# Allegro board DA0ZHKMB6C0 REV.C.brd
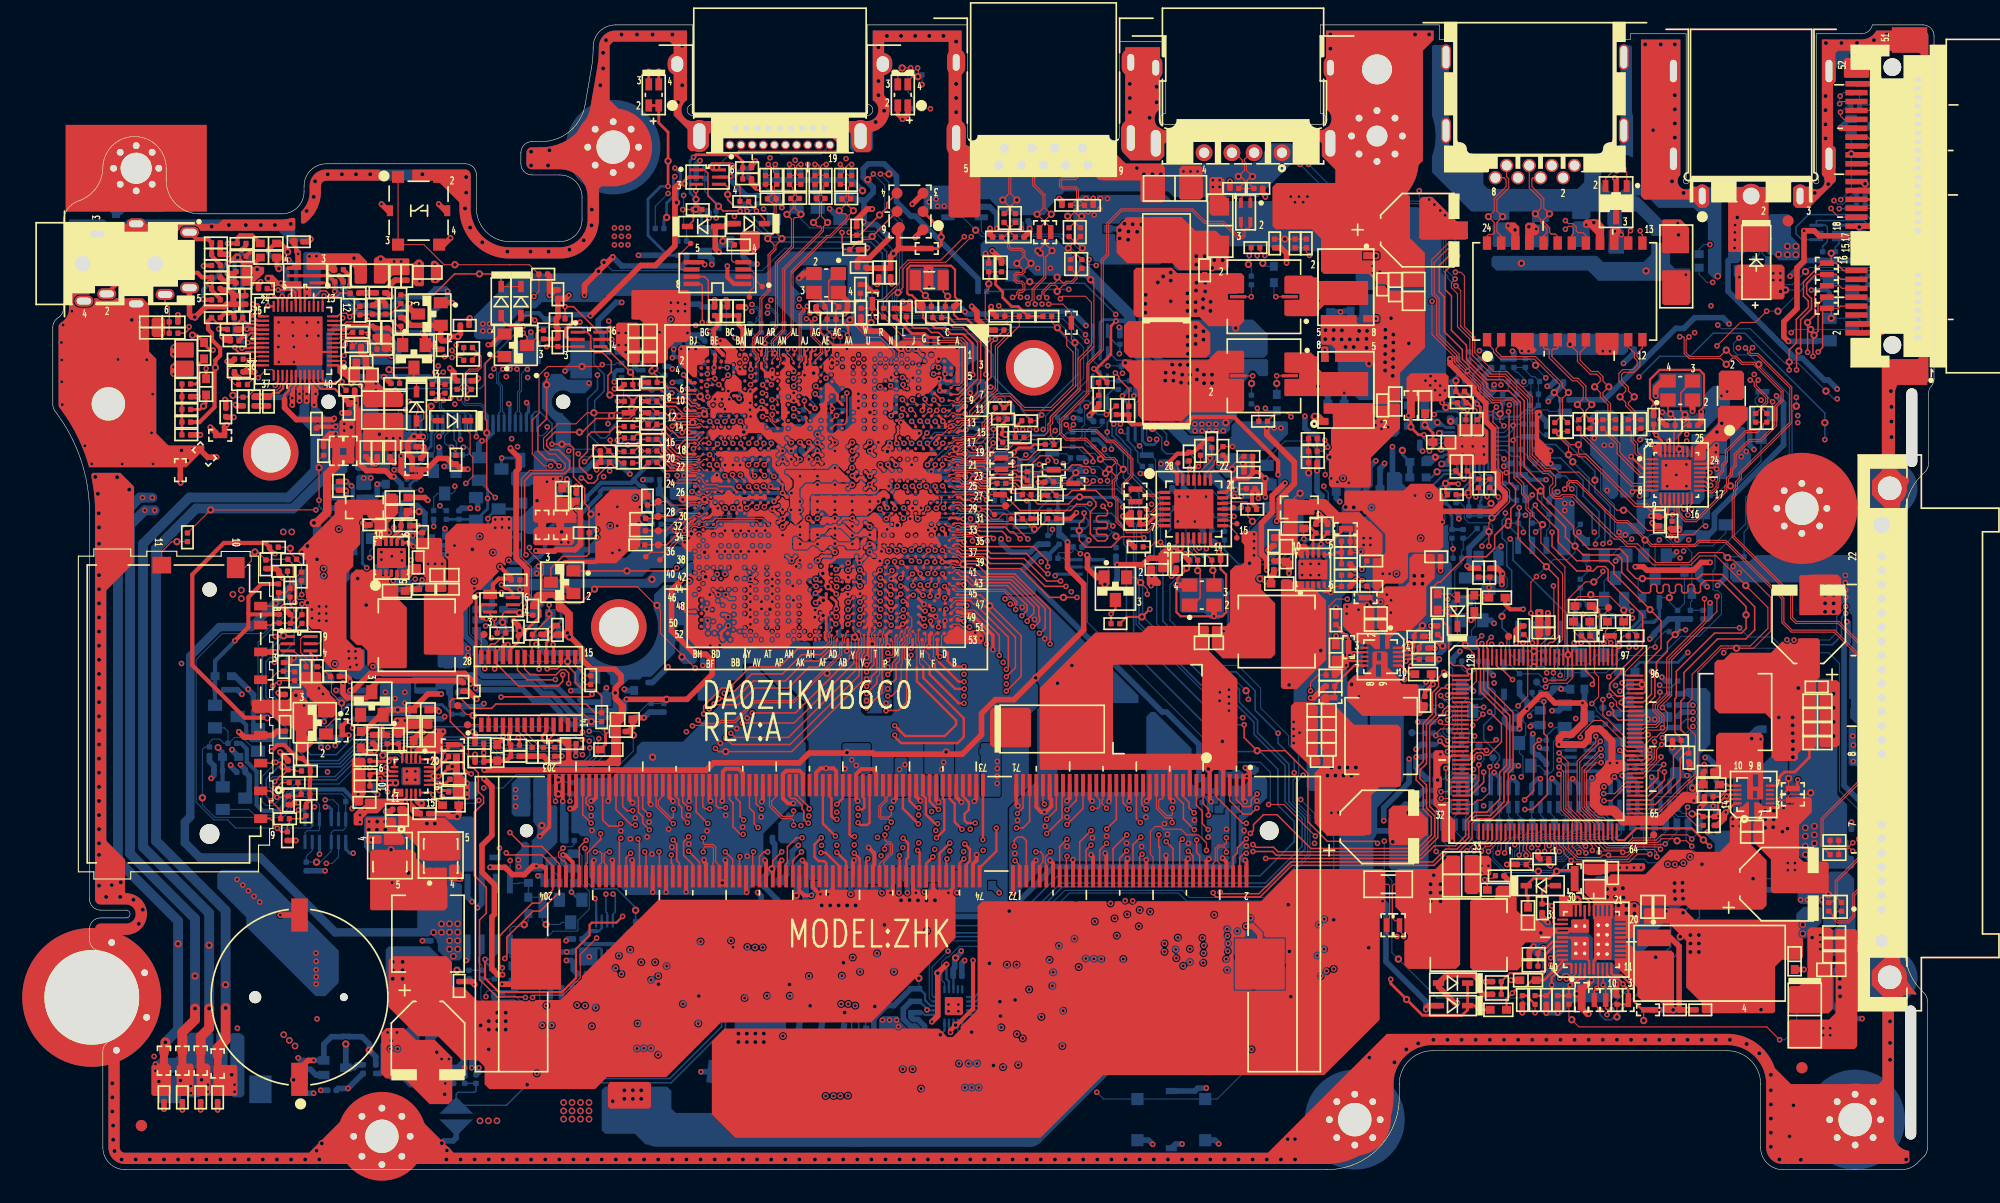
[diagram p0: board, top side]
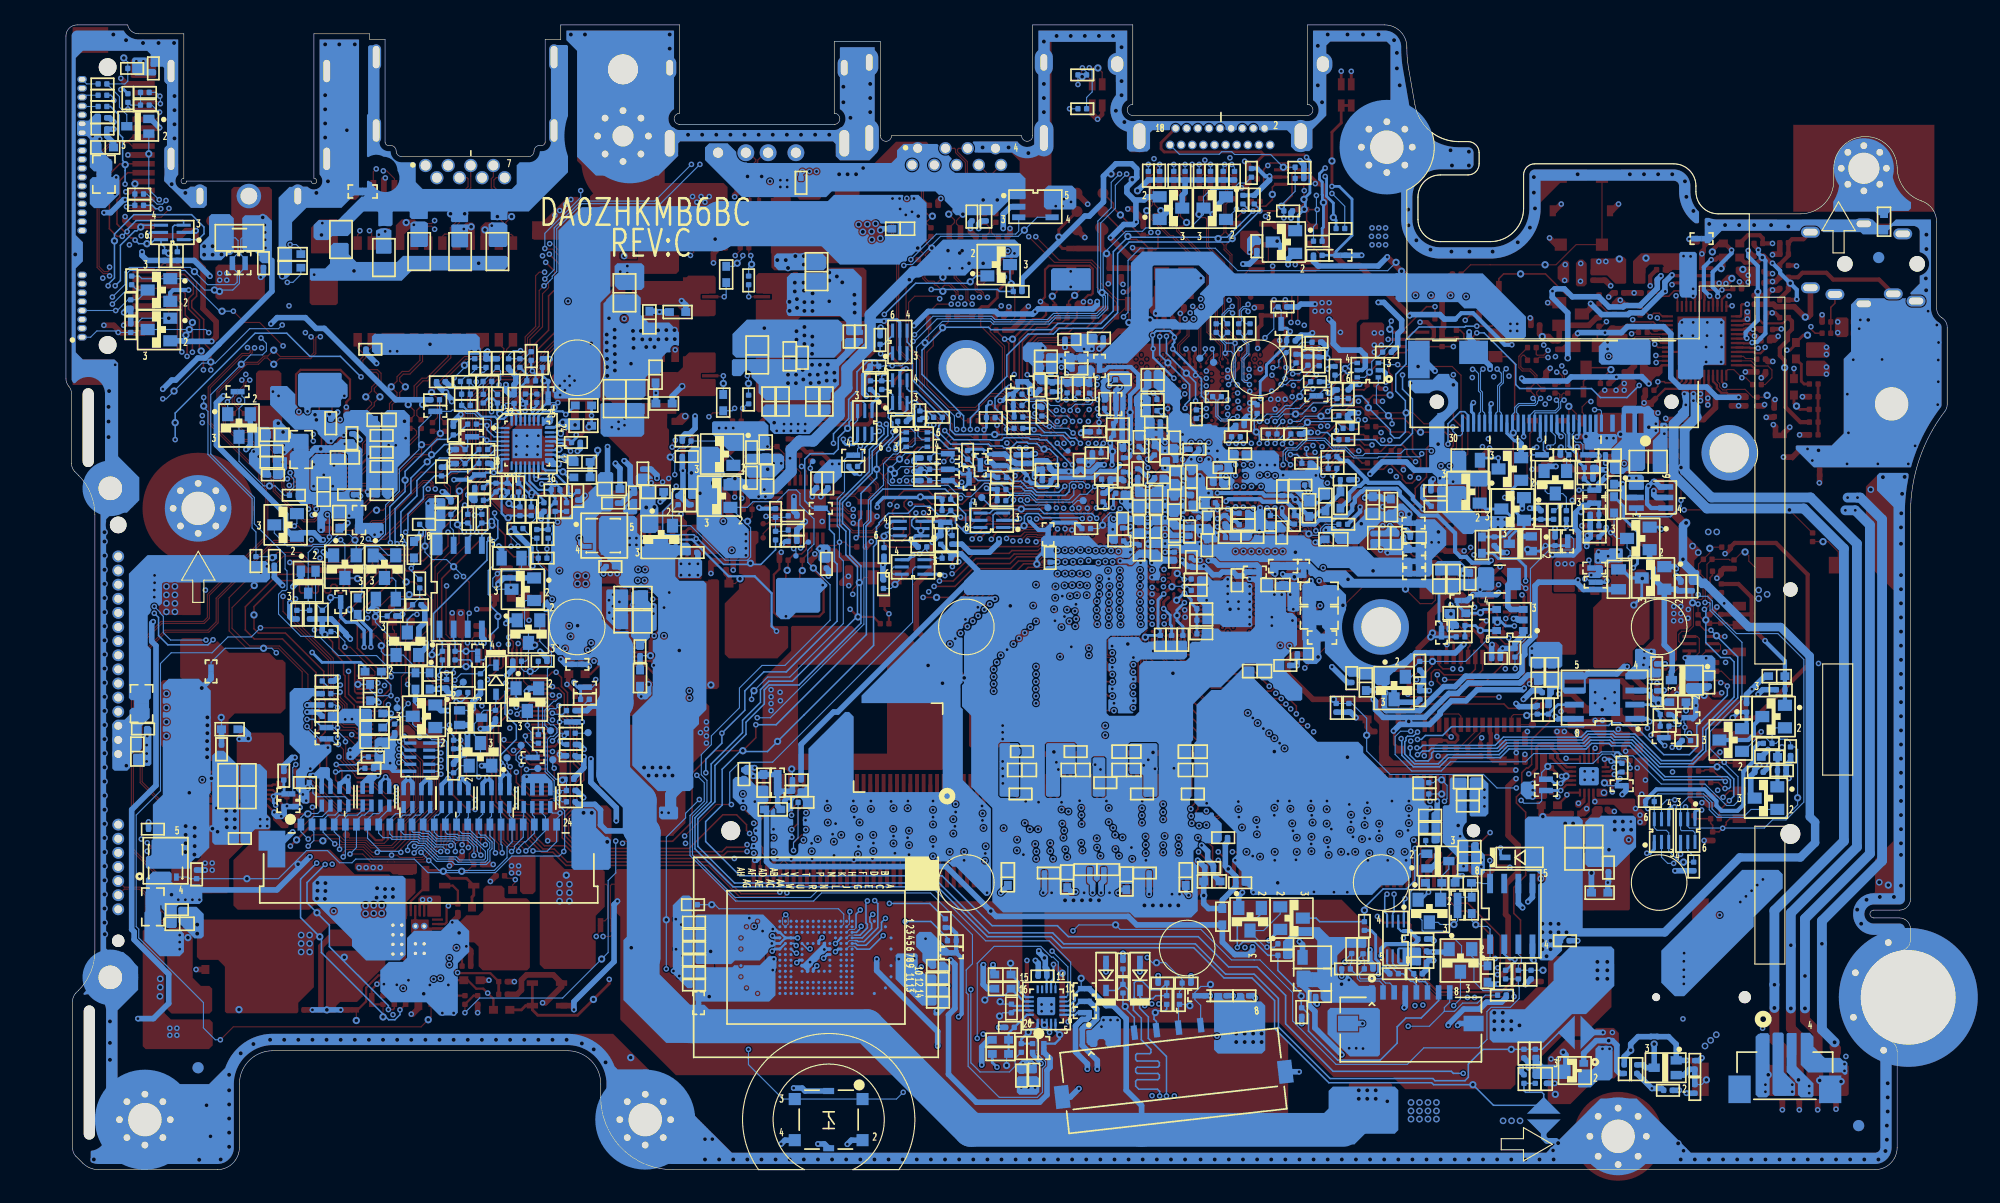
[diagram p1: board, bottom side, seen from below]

Outline 169.2 x 103 mm; copper layers: TOP, SGND, IN1, IN2, SVCC, BOTTOM. Coordinates in mm from the lower left corner of the outline.
Outline path: 0,75.8 arc(0.13,76.28) 0.47,76.65 arc(0.82,77.01) 0.95,77.5 0.95,85.27 arc(1.33,86.44) 2.32,87.17 arc(3.88,88.31) 4.5,90.15 arc(7.37,92.95) 10.2,90.1 10.2,89 arc(11.08,86.88) 13.2,86 20.6,86 arc(22.01,86.59) 22.6,88 22.6,88.5 arc(23.19,89.91) 24.6,90.5 37.1,90.5 arc(37.81,90.21) 38.1,89.5 38.1,86.5 arc(38.98,84.38) 41.1,83.5 45.6,83.5 arc(47.01,84.09) 47.6,85.5 47.6,87.5 arc(47.01,88.91) 45.6,89.5 43.1,89.5 arc(42.39,89.79) 42.1,90.5 42.1,91.5 arc(42.39,92.21) 43.1,92.5 43.93,92.5 arc(46.51,93.44) 47.87,95.82 48.45,99.15 arc(48.56,100) 48.6,100.86 48.6,101 arc(49.19,102.41) 50.6,103 57.55,103 57.55,95.85 arc(57.05,95.35) 57.55,94.85 73.25,94.85 arc(73.75,95.35) 73.25,95.85 73.25,103 82.25,103 82.25,93.03 arc(82.75,92.53) 83.25,93.03 94.95,93.03 arc(95.45,92.53) 95.95,93.03 95.95,101.5 100.1,101.5 100.1,95.05 arc(99.6,94.55) 100.1,94.05 114,94.05 arc(114.5,94.55) 114,95.05 114,103 124.7,103 124.7,101.7 126.1,101.7 126.1,92.45 arc(126.19,92.24) 126.4,92.15 126.6,92.15 arc(126.95,92) 127.1,91.65 arc(127.25,91.3) 127.6,91.15 139,91.15 arc(139.35,91.3) 139.5,91.65 arc(139.65,92) 140,92.15 140.2,92.15 arc(140.41,92.24) 140.5,92.45 140.5,101.7 141.9,101.7 141.9,102.2 146.9,102.2 146.9,89.2 arc(146.72,88.77) 147.15,88.95 158.35,88.95 arc(158.78,88.77) 158.6,89.2 158.6,102.2 162.67,102.2 arc(163.3,102.43) 163.65,103 168.2,103 arc(168.91,102.71) 169.2,102 169.2,71.16 arc(169.14,70.8) 168.95,70.5 arc(168.76,70.19) 168.7,69.83 168.7,63.51 arc(168.62,63.13) 168.41,62.81 168.06,62.46 arc(166.98,60.84) 166.6,58.93 166.6,19.67 arc(166.98,17.76) 168.06,16.14 168.31,15.89 arc(168.52,15.57) 168.6,15.19 168.6,1.91 arc(168.52,1.53) 168.31,1.21 167.69,0.59 arc(167.04,0.15) 166.27,0 155.6,0 arc(154.19,0.59) 153.6,2 153.6,7.7 arc(152.72,9.82) 150.6,10.7 124.1,10.7 arc(121.98,9.82) 121.1,7.7 121.1,6.5 arc(119.2,1.9) 114.6,0 6.5,0 arc(5.09,0.59) 4.5,2 4.5,10.65 arc(4.67,11.2) 5.12,11.57 arc(7.72,16) 4.15,19.7 arc(3.54,20.04) 3.3,20.69 3.3,21.65 arc(3.59,22.36) 4.3,22.65 6.6,22.65 arc(6.95,23) 6.6,23.35 4.3,23.35 arc(3.59,23.64) 3.3,24.35 3.3,59.11 arc(2.51,63.93) 0.21,68.24 arc(0.05,68.52) 0,68.85 0,75.8

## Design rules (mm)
constraint set DEFAULT: min track width 0.102
net group DFP-S3(3.5)W4(4)-T2B: nets C_TX1_HDMI+ C_TX1_HDMI-
net group DFP-S3W4-TB: nets SOC_PCIE_COMN SOC_PCIE_COMP
net group W5.5-T12B: nets PCH_DPST_PWM PCH_DPST_PWM_C
net group DFP-S3(3.5)W4(4)-T1: nets IN_CLK IN_CLK# IN_D0 IN_D0# IN_D1 IN_D1# IN_D2 IN_D2# SATA_RXN0 SATA_RXN0_R SATA_RXP0 SATA_RXP0_R SATA_TXN0 SATA_TXN0_R SATA_TXP0 SATA_TXP0_R
net group DFP-S3(3.5)W4(4)-T1B: nets C_TX0_HDMI+ C_TX0_HDMI- C_TX2_HDMI+ C_TX2_HDMI- C_TXC_HDMI+ C_TXC_HDMI- CLK_PCIE_LANN CLK_PCIE_LANP CLK_PCIE_WLANN CLK_PCIE_WLANP EDP_TX0#_C EDP_TX0_C GPP_TX2N_LAN GPP_TX2P_LAN ICLK_USB_TERMN_0 ICLK_USB_TERMN_1 INT_EDP_TXN0 INT_EDP_TXP0 PCIE_RXN1_WLAN PCIE_RXN2_LAN PCIE_RXP1_WLAN PCIE_RXP2_LAN PCIE_TXN1_WLAN PCIE_TXN1_WLAN_C PCIE_TXN2_LAN PCIE_TXN2_LAN_C PCIE_TXP1_WLAN PCIE_TXP1_WLAN_C PCIE_TXP2_LAN PCIE_TXP2_LAN_C USB30_RX1+ USB30_RX1+_R USB30_RX1- USB30_RX1-_R USB30_TX1+ USB30_TX1+_R USB30_TX1- USB30_TX1-_R USB_BT_N USB_BT_P USB_H1_N USB_H1_N1 USB_H1_P USB_H1_P1 USB_USB_N USB_USB_P USBP1+_CN USBP1-_CN
net group DFP-S3(3.5)W4(4)-T12B: nets M_A_CLKN0 M_A_CLKN1 M_A_CLKP0 M_A_CLKP1 M_A_DQSN0 M_A_DQSN1 M_A_DQSN2 M_A_DQSN3 M_A_DQSN4 M_A_DQSN5 M_A_DQSN6 M_A_DQSN7 M_A_DQSP0 M_A_DQSP1 M_A_DQSP2 M_A_DQSP3 M_A_DQSP4 M_A_DQSP5 M_A_DQSP6 M_A_DQSP7 SATA_RCOMP_DN SATA_RCOMP_DP SOC_DDIO_RCOMP SOC_DDIO_RCOMP_P
net group DFP-S5.5(6)W4(3.5)-T1B: nets LAN_MX0+ LAN_MX0- LAN_MX1+ LAN_MX1- LAN_MX2+ LAN_MX2- LAN_MX3+ LAN_MX3- MDI_0+ MDI_0+_C MDI_0- MDI_0-_C MDI_1+ MDI_1+_C MDI_1- MDI_1-_C MDI_2+ MDI_2+_C MDI_2- MDI_2-_C MDI_3+ MDI_3+_C MDI_3- MDI_3-_C
net group DFP-S5W10-T12B: nets VCC_AXG_SENSE VCC_SENSE VSS_AXG_SENSE VSS_SENSE
net group W5.5(5.5)-T1: nets ACZ_BCLK ACZ_RST# ACZ_RST#_AUDIO ACZ_SDIN ACZ_SDIN0 ACZ_SDOUT ACZ_SDOUT_AUDIO ACZ_SYNC ACZ_SYNC_AUDIO BIT_CLK_AUDIO
net group W5.5(5.5)-T12B: nets 5V_HSMBCK 5V_HSMBDT 8690_CLK 8690_DATA AC_PRESENT AC_PRESENT_EC AC_PRESENT_NM ACZ_RST#_AUDIO_R ACZ_SPKR BEEP_1 BRTC_EXTPAD CLK_24M_DEBUG CLK_24M_KBC CLKRUN# DMIC_CLK DMIC_DAT DNBSWON# EMMC_CLK EMMC_CMD EMMC_DATA_0 EMMC_DATA_1 EMMC_DATA_2 EMMC_DATA_3 EMMC_DATA_4 EMMC_DATA_5 EMMC_DATA_6 EMMC_DATA_7 EMMC_RCOMP EMMC_RESET H_PROCHOT# HDA_RCOMP HDMI_SCLK HDMI_SDATA I2C_0_SCL I2C_0_SDA I2C_5_SCL I2C_5_SDA I2C_6_SCL I2C_6_SCL_R I2C_6_SDA I2C_6_SDA_R ICLK_ICOMP ICLK_RCOMP LAD0 LAD1 LAD2 LAD3 LFRAME# LPC_RCOMP M_A_DM0 M_A_DM1 M_A_DM2 M_A_DM3 M_A_DM4 M_A_DM5 M_A_DM6 M_A_DM7 M_A_DQ0 M_A_DQ1 M_A_DQ2 M_A_DQ3 M_A_DQ4 M_A_DQ5 M_A_DQ6 M_A_DQ7 M_A_DQ8 M_A_DQ9 M_A_DQ10 M_A_DQ11 M_A_DQ12 M_A_DQ13 M_A_DQ14 M_A_DQ15 M_A_DQ16 M_A_DQ17 M_A_DQ18 M_A_DQ19 M_A_DQ20 M_A_DQ21 M_A_DQ22 M_A_DQ23 M_A_DQ24 M_A_DQ25 M_A_DQ26 M_A_DQ27 M_A_DQ28 M_A_DQ29 M_A_DQ30 M_A_DQ31 M_A_DQ32 M_A_DQ33 M_A_DQ34 M_A_DQ35 M_A_DQ36 M_A_DQ37 M_A_DQ38 M_A_DQ39 M_A_DQ40 M_A_DQ41 M_A_DQ42 M_A_DQ43 M_A_DQ44 M_A_DQ45 M_A_DQ46 M_A_DQ47 M_A_DQ48 M_A_DQ49 M_A_DQ50 M_A_DQ51 M_A_DQ52 M_A_DQ53 M_A_DQ54 M_A_DQ55 M_A_DQ56 M_A_DQ57 M_A_DQ58 M_A_DQ59 M_A_DQ60 M_A_DQ61 M_A_DQ62 M_A_DQ63 MBCLK MBCLK2 MBDATA MBDATA2 N16563782 N16563868 N16564009 N77651966 PCBEEP PCBEEP_EC PCH_SLP_S0# PCH_SLP_S0_N PCLK_TPM PLTRST# RSMRST# RTC_X1 RTC_X2 SDIO3_CLK SDIO3_CMD SDIO3_DATA_0 SDIO3_DATA_1 SDIO3_DATA_2 SDIO3_DATA_3 SDIO3_RCOMP SDVO_CLK SDVO_DATA SERIRQ_R SLP_S0IX# SLP_S3# SLP_S4# SMB_RUN_CLK SMB_RUN_DAT SMB_SOC_CLK SMB_SOC_DATA SMC SMD SOC_CLKOUT_0 SOC_CLKOUT_1 SOC_CLKRUN# SOC_PLTRST# SOC_PROCHOT# SOC_PWRBTN# SOC_REST_BTN SOC_SERIRQ SOC_SPI_CLK SOC_SPI_CLK_R SOC_SPI_CLK_R1 SOC_SPI_CS# SOC_SPI_CS#_R SOC_SPI_CS#_R1 SOC_SPI_MISO SOC_SPI_MISO_R SOC_SPI_MISO_R1 SOC_SPI_MOSI SOC_SPI_MOSI_R SOC_SPI_MOSI_R1 SUS_PWRDOWNACK SUSB# SUSC# SUSWARN#_EC SVID_ALERT#_SOC SVID_CLK_SOC SVID_DATA_SOC VR_SVID_ALERT# VR_SVID_CLK VR_SVID_DATA WLAN_CLK_SCLK WLAN_CLK_SDATA XIN XOUT XTAL1 XTAL2 XTAL25_IN XTAL25_OUT
net group W8.5(8)-T12B: nets M_A_A0 M_A_A1 M_A_A2 M_A_A3 M_A_A4 M_A_A5 M_A_A6 M_A_A7 M_A_A8 M_A_A9 M_A_A10 M_A_A11 M_A_A12 M_A_A13 M_A_A14 M_A_A15 M_A_BS#0 M_A_BS#1 M_A_BS#2 M_A_CAS# M_A_CKE0 M_A_CKE1 M_A_CS#0 M_A_CS#1 M_A_ODT0 M_A_ODT1 M_A_RAS# M_A_WE#
net group W10-T12B: nets +1.8V_S5 +1.35V +3V_MINI1_VDD +VSDIO CPU_VREF DRAM_RCOMP0 DRAM_RCOMP1 DRAM_RCOMP2 HDMI_5V MIC1_INT_L MIC1_INT_L_C MIC1_INT_R MIC1_INT_R_C MIC1_INTL1 PCU_V3P3_G3_PWR TPM_VDD USB_HSIC_RCOMP
net group W15-T12B: nets +1.8V +3V_USB HPL HPL-1_TIP_SENSE HPR HPR_SYS INT_AMIC-VREFO LINE1-L LINE1-R LINE1-VREFO-L LINE1-VREFO-R MIC2-VREFO USB3_V1P0_G3 USB_RCOMP
net group W20-T12B: nets +3V_RTC +3V_S5 CCD_PWR VCCRTC_1 VCCRTC_2 VCCRTC_3 VCCRTC_4
net group W30-T12B: nets +3VPCU_EC CODEC_VREF LAN_MCT0 LAN_MCT1 LAN_MCT2 LAN_MCT3
net group W35-T12B: nets L_SPK+ L_SPK+_1 L_SPK- L_SPK-_1 MIC2_MIC_RING2_MIC MIC2_MIC_SLEEVE_MIC R_SPK+ R_SPK+_1 R_SPK- R_SPK-_1 RING2 SLEEVE
net group W40-T12B: nets +5VA LANVCC REGOUT VDD10 VDDREG/VDD33
net group W60-T12B: nets V_BLIGHT
net group W80-T12B: nets 5VUSB_0 +5V_HDD +LCDVCC
net group W90-T12B: nets LANCT3

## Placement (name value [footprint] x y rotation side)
C4  em@0.1u/10v_4  [CC0402]  112.71 16.6 0 bottom
C5  em@1u/6.3v_4  [CC0402]  90.79 16.08 0 bottom
C7  *220p/50v_4  [CC0402]  62.45 89.14 180 top
C8  0.1u/10v_4  [CC0402]  64.1 89.05 270 top
C9  0.1u/10v_4  [CC0402]  65.12 89.05 270 top
C10  0.1u/10v_4  [CC0402]  66.26 89.05 270 top
C11  0.1u/10v_4  [CC0402]  67.28 89.05 270 top
C12  0.1u/10v_4  [CC0402]  68.55 89.05 270 top
C13  0.1u/10v_4  [CC0402]  69.56 89.05 270 top
C14  0.1u/10v_4  [CC0402]  70.83 89.05 270 top
C15  0.1u/10v_4  [CC0402]  71.85 89.05 270 top
C16  10u/6.3v_4  [CC0402]  75.35 80.72 270 top
C17  *1.6p/50v_4  [CC0402]  91.15 86.77 0 top
C18  *1.6p/50v_4  [CC0402]  93.18 86.77 180 top
C19  0.1u/10v_4  [CC0402]  74.29 80.72 270 top
C20  100u/6.3v_1206  [CC1206]  100.93 88.29 0 top
C21  100u/6.3v_1206  [CC1206]  104.99 84.94 270 top
C22  *1.6p/50v_4  [CC0402]  84.93 83.91 0 top
C23  *1.6p/50v_4  [CC0402]  86.97 83.91 180 top
C24  330p/50v_4  [CC0402]  14.67 79.27 0 top
C25  0.1u/10v_4  [CC0402]  91.53 81.48 270 top
C26  0.1u/10v_4  [CC0402]  92.55 81.48 270 top
C27  *1000p/50v_4  [CC0402]  22.11 83.49 180 top
C28  220p/3kv_1808  [CC1808]  146.02 81.31 90 top
C30  em@0.1u/10v_4  [CC0402]  90.77 15.06 180 bottom
C31  330p/50v_4  [CC0402]  8.83 75.26 180 top
C32  12p/50v_4  [CC0402]  69.05 77.62 0 top
C33  12p/50v_4  [CC0402]  71.09 77.62 180 top
C34  em@0.1u/10v_4  [CC0402]  112.71 19.98 0 bottom
C35  10u/6.3v_4  [CC0402]  18.89 79.27 0 top
C36  10u/6.3v_4  [CC0402]  16.86 80.8 0 top
C37  *1000p/50v_4  [CC0402]  29.48 78.89 180 top
C38  0.01u/16v_4  [CC0402]  45.43 78.77 270 top
C39  0.1u/10v_4  [CC0402]  16.86 79.78 0 top
C40  1u/10v_4  [CC0402]  27.63 77.29 90 top
C41  100p/50v_4  [CC0402]  29.91 77.37 270 top
C42  1u/6.3v_4  [CC0402]  59.53 77.24 90 top
C43  1u/6.3v_4  [CC0402]  60.67 77.24 90 top
C44  1u/6.3v_4  [CC0402]  61.69 77.24 270 top
C45  0.1u/10v_4  [CC0402]  76.78 77.11 270 top
C46  15p/50v_4  [CC0402]  80.66 77.67 0 top
C47  15p/50v_4  [CC0402]  78.63 77.67 180 top
C48  330p/50v_4  [CC0402]  14.67 83.39 0 top
C49  10u/6.3v_4  [CC0402]  16.7 76.66 0 top
C50  10u/6.3v_6  [CC0603]  53.05 75.46 0 top
C51  0.1u/10v_4  [CC0402]  29 75.34 90 top
C52  10u/6.3v_4  [CC0402]  30.09 75.34 90 top
C53  2.2u/6.3v_4  [CC0402]  16.09 75.59 180 top
C55  *22p/50v_4  [CC0402]  27.32 74.04 0 top
C56  10u/6.3v_4  [CC0402]  29.56 73.81 180 top
C57  1u/10v_4  [CC0402]  16.73 72.92 0 top
C58  10u/6.3v_6  [CC0603]  53.05 72.92 0 top
C59  0.1u/10v_4  [CC0402]  27.75 72.7 180 top
C60  em@1u/6.3v_4  [CC0402]  90.8 17.2 0 bottom
C61  10u/6.3v_4  [CC0402]  16.73 71.78 0 top
C62  10u/6.3v_6  [CC0603]  27.96 71.5 180 top
C63  1u/10v_4  [CC0402]  17.11 70.64 0 top
C64  0.1u/10v_4  [CC0402]  37.35 72.82 0 top
C65  0.1u/10v_4  [CC0402]  37.35 73.97 0 top
C66  0.1u/10v_4  [CC0402]  34.13 70.26 270 top
C67  0.1u/10v_4  [CC0402]  35.27 70.26 270 top
C68  10u/6.3v_4  [CC0402]  17.11 69.11 270 top
C69  0.1u/10v_4  [CC0402]  18.13 69.11 90 top
C70  10u/6.3v_4  [CC0402]  19.4 69.11 90 top
C71  0.1u/10v_4  [CC0402]  23.71 67.11 90 top
C72  0.1u/10v_4  [CC0402]  26.64 68.48 90 top
C73  22u/6.3v_8  [CC0805]  28.79 68.35 270 top
C74  2.2u/10v_8  [CC0805]  30.83 68.35 90 top
C75  em@0.1u/10v_4  [CC0402]  112.71 17.72 0 bottom
C76  0.1u/10v_4  [CC0402]  153.15 67.64 270 top
C77  0.1u/10v_4  [CC0402]  154.17 67.64 270 top
C78  12p/50v_4  [CC0402]  145.53 66.98 0 top
C79  12p/50v_4  [CC0402]  147.57 66.98 180 top
C80  *22p/50v_4  [CC0402]  20.74 45.24 270 top
C82  1000p/50v_4  [CC0402]  32.3 65.05 0 top
C83  *0.1u/10v_4  [CC0402]  28.16 64.54 270 top
C84  0.1u/10v_4  [CC0402]  29.18 64.54 270 top
C85  0.01u/25v_4  [CC0402]  30.32 64.54 90 top
C86  *10p/50v_4  [CC0402]  32.71 64.01 180 top
C87  0.1u/10v_4  [CC0402]  107.53 62.76 180 top
C89  1u/6.3v_4  [CC0402]  25.7 61.53 90 top
C90  1u/6.3v_4  [CC0402]  97.37 59.08 180 top
C91  0.1u/10v_4  [CC0402]  144.49 58.32 90 top
C92  1u/6.3v_4  [CC0402]  97.37 58.06 180 top
C94  0.1u/10v_4  [CC0402]  101.06 54.51 270 top
C95  18p/50v_4  [CC0402]  102.58 54.84 0 top
C96  18p/50v_4  [CC0402]  104.64 54.84 180 top
C97  0.1u/10v_4  [CC0402]  128.24 53.72 270 top
C98  0.1u/10v_4  [CC0402]  129.25 53.72 270 top
C101  4.7u/6.3v_6  [CC0603]  127.85 50.95 270 top
C102  0.1u/10v_4  [CC0402]  134.08 49.3 180 top
C103  10u/6.3v_6  [CC0603]  137.51 49.3 0 top
C104  *10u/6.3v_6  [CC0603]  140.55 49.3 0 top
C105  tpm@0.1u/10v_4  [CC0402]  41.88 48.41 270 top
C106  *10p/50v_4  [CC0402]  43.53 48.16 180 top
C107  tpm@0.1u/10v_4  [CC0402]  45.38 48.57 270 top
C108  0.1u/10v_4  [CC0402]  134.08 48.29 180 top
C109  0.1u/10v_4  [CC0402]  137.89 48.03 0 top
C110  0.01u/25v_4  [CC0402]  142.08 48.03 0 top
C115  *330u/2v_7343  [CC7343]  89.88 39.65 0 top
C118  tpm@0.1u/10v_4  [CC0402]  46.68 38.33 180 top
C119  tpm@0.1u/10v_4  [CC0402]  51.1 39.42 180 top
C123  hd@0.01u/16v_4  [CC0402]  160.24 29.62 0 top
C124  hd@0.01u/16v_4  [CC0402]  160.24 28.35 0 top
C125  0.1u/10v_4  [CC0402]  134.15 27.97 180 top
C126  1u/6.3v_4  [CC0402]  132.12 27.46 0 top
C127  *0.1u/25v_4  [CC0402]  143.35 23.65 90 top
C128  *1000p/50v_4  [CC0402]  144.49 23.65 270 top
C129  hd@0.01u/16v_4  [CC0402]  159.73 23.65 270 top
C130  hd@0.01u/16v_4  [CC0402]  160.87 23.65 270 top
C131  *0.1u/16v_4  [CC0402]  160.21 21.41 180 top
C132  hd@0.01u/25v_4  [CC0402]  160.21 20.27 180 top
C133  *0.1u/16v_4  [CC0402]  160.21 19.13 180 top
C134  hd@10u/6.3v_6  [CC0603]  159.96 17.98 180 top
C135  *100u/6.3v_3528  [CC3528]  157.57 13.87 90 top
C136  *68p/50v_4  [CC0402]  10 6.5 90 top
C137  *68p/50v_4  [CC0402]  11.65 6.5 90 top
C138  *68p/50v_4  [CC0402]  13.3 6.5 90 top
C139  *68p/50v_4  [CC0402]  14.82 6.5 90 top
C140  *0.1u/10v_4  [CC0402]  161.34 99.09 90 bottom
C141  *0.1u/10v_4  [CC0402]  165.91 94.64 180 bottom
C142  0.1u/10v_4  [CC0402]  165.91 93.62 180 bottom
C143  10u/6.3v_6  [CC0603]  165.66 91.97 0 bottom
C144  220p/50v_4  [CC0402]  58.26 90.2 0 bottom
C145  0.1u/10v_4  [CC0402]  103.09 88.8 270 bottom
C146  4.7u/10v_6  [CC0603]  94.17 84.66 0 bottom
C147  4.7u/6.3v_4  [CC0402]  20.9 42.37 270 top
C148  0.1u/10v_4  [CC0402]  86.45 85.75 270 bottom
C149  470p/50v_4  [CC0402]  87.72 85.75 270 bottom
C151  0.1u/10v_4  [CC0402]  69.78 63.86 180 bottom
C152  0.1u/10v_4  [CC0402]  65.75 75.72 90 bottom
C153  0.1u/10v_4  [CC0402]  64.74 75.72 90 bottom
C154  0.1u/10v_4  [CC0402]  62.7 75.72 90 bottom
C155  0.1u/10v_4  [CC0402]  63.72 75.72 90 bottom
C156  0.1u/10v_4  [CC0402]  25.37 44.37 0 top
C157  0.1u/10v_4  [CC0402]  20.9 39.83 270 top
C158  10u/6.3v_6  [CC0603]  53.05 74.22 180 top
C159  *1000p/50v_4  [CC0402]  97.76 74.96 270 bottom
C160  *0.1u/10v_4  [CC0402]  98.77 74.96 90 bottom
C161  0.01u/25v_4  [CC0402]  76.29 74.83 0 bottom
C162  1u/6.3v_4  [CC0402]  78.96 74.7 0 bottom
C164  0.01u/50v_4  [CC0402]  141.82 73.81 0 bottom
C165  1u/6.3v_4  [CC0402]  81.06 73.2 0 bottom
C167  4.7u/6.3v_6  [CC0603]  104.11 73.18 90 bottom
C170  1u/6.3v_4  [CC0402]  81.63 70.56 90 bottom
C171  1u/6.3v_4  [CC0402]  81.06 72.19 180 bottom
C172  0.01u/25v_4  [CC0402]  78.32 72.04 180 bottom
C173  1u/6.3v_4  [CC0402]  71.46 71.55 0 bottom
C174  0.01u/25v_4  [CC0402]  71.46 70.54 0 bottom
C175  22u/6.3v_6  [CC0603]  100.8 69.11 270 bottom
C176  2.2u/6.3v_6  [CC0603]  102.07 69.11 270 bottom
C178  22u/6.3v_6  [CC0603]  104.74 69.11 270 bottom
C179  22u/6.3v_6  [CC0603]  106.01 69.11 270 bottom
C180  4.7u/6.3v_6  [CC0603]  140.81 67.46 180 bottom
C181  *1u/6.3v_4  [CC0402]  71.16 67.26 0 bottom
C182  0.1u/10v_4  [CC0402]  145.38 67.16 270 bottom
C183  0.1u/10v_4  [CC0402]  74.59 67.11 0 bottom
C184  4.7u/6.3v_6  [CC0603]  150.44 66.12 0 bottom
C185  1u/6.3v_4  [CC0402]  74.59 66.09 180 bottom
C186  0.1u/10v_4  [CC0402]  140.81 66.07 180 bottom
C187  0.1u/10v_4  [CC0402]  143.48 65.81 270 bottom
C188  1u/6.3v_4  [CC0402]  72.68 65.46 90 bottom
C189  1u/6.3v_4  [CC0402]  69.49 65.43 270 bottom
C190  0.01u/25v_4  [CC0402]  30.34 64.31 180 bottom
C191  1u/6.3v_4  [CC0402]  67.71 64.82 0 bottom
C192  *4.7u/25v_8  [CC0805]  26.89 63.7 0 bottom
C193  1u/6.3v_4  [CC0402]  71.31 64.7 270 bottom
C194  1u/6.3v_4  [CC0402]  76.49 64.49 0 bottom
C195  0.1u/10v_4  [CC0402]  150.71 64.67 0 bottom
C196  0.1u/10v_4  [CC0402]  140.81 64.54 0 bottom
C197  1u/6.3v_4  [CC0402]  74.09 64.44 270 bottom
C198  4.7u/6.3v_6  [CC0603]  144.11 64.08 0 bottom
C199  1u/6.3v_4  [CC0402]  82.71 63.93 90 bottom
C200  1u/6.3v_4  [CC0402]  83.73 63.93 90 bottom
C202  1000p/50v_4  [CC0402]  32.25 63.17 180 bottom
C203  0.1u/10v_4  [CC0402]  150.71 63.65 180 bottom
C204  0.1u/10v_4  [CC0402]  140.81 63.27 0 bottom
C205  1u/6.3v_4  [CC0402]  78.07 63.4 90 bottom
C206  0.1u/50v_6  [CC0603]  29.96 62.41 270 bottom
C207  0.01u/25v_4  [CC0402]  80.99 63.02 0 bottom
C208  1u/6.3v_4  [CC0402]  64.99 63.17 0 bottom
C209  1u/6.3v_4  [CC0402]  72.81 62.66 90 bottom
C210  *10p/50v_4  [CC0402]  32.25 62.15 0 bottom
C211  1u/6.3v_4  [CC0402]  150.59 62.51 180 bottom
C214  1u/6.3v_4  [CC0402]  67.98 62.36 90 bottom
C215  1u/6.3v_4  [CC0402]  63.59 64.41 0 bottom
C216  1u/6.3v_4  [CC0402]  65.57 61.77 180 bottom
C217  1u/6.3v_4  [CC0402]  63.62 66.95 180 bottom
C218  1u/6.3v_4  [CC0402]  69.38 62.26 270 bottom
C219  1u/6.3v_4  [CC0402]  70.91 62.26 0 bottom
C220  1u/6.3v_4  [CC0402]  74.08 62.38 270 bottom
C221  1u/6.3v_4  [CC0402]  80.99 62 0 bottom
C222  10u/6.3v_4  [CC0402]  100.68 61.75 270 bottom
C223  0.1u/10v_4  [CC0402]  101.69 61.75 270 bottom
C224  1u/6.3v_4  [CC0402]  59.78 61.04 90 bottom
C225  4.7u/6.3v_6  [CC0603]  146.02 60.99 90 bottom
C226  *1u/10v_4  [CC0402]  37.05 75.97 0 top
C227  0.1u/10v_4  [CC0402]  140.81 60.73 0 bottom
C228  0.1u/10v_4  [CC0402]  143.73 60.73 0 bottom
C229  1u/6.3v_4  [CC0402]  67.98 60.33 90 bottom
C230  4.7u/6.3v_6  [CC0603]  71.16 60.25 90 bottom
C231  2.2u/6.3v_6  [CC0603]  72.68 60.25 90 bottom
C232  22u/6.3v_6  [CC0603]  50.03 59.61 270 bottom
C233  22u/6.3v_6  [CC0603]  51.65 59.82 270 bottom
C234  0.1u/10v_4  [CC0402]  66.22 60 180 bottom
C235  *22uf/6.3v_6  [CC0603]  55.92 60 270 bottom
C236  *22uf/6.3v_6  [CC0603]  57.4 59.51 270 bottom
C237  10u/6.3v_6  [CC0603]  69.51 59.87 90 bottom
C238  0.1u/10v_4  [CC0402]  134.97 60.1 180 bottom
C239  1u/6.3v_4  [CC0402]  63.29 59.06 0 bottom
C240  1u/6.3v_4  [CC0402]  58.71 58.47 270 bottom
C241  1u/6.3v_4  [CC0402]  64.93 58.47 270 bottom
C242  10u/6.3v_6  [CC0603]  144.62 58.45 270 bottom
C243  1u/6.3v_4  [CC0402]  74.16 58.12 90 bottom
C244  0.1u/10v_4  [CC0402]  66.46 58.22 270 bottom
C245  1u/6.3v_4  [CC0402]  63.28 58.03 180 bottom
C246  0.01u/25v_4  [CC0402]  71.18 57.84 90 bottom
C247  1u/6.3v_4  [CC0402]  72.68 57.84 90 bottom
C248  0.1u/10v_4  [CC0402]  103.85 57.56 180 bottom
C249  1u/6.3v_4  [CC0402]  68.14 57.41 90 bottom
C250  0.47uf/4v_4  [CC0402]  69.51 57.46 90 bottom
C251  1u/6.3v_4  [CC0402]  59.85 57.33 270 bottom
C252  1u/6.3v_4  [CC0402]  51.6 56.85 270 bottom
C253  1u/6.3v_4  [CC0402]  62.5 56.87 180 bottom
C254  1u/6.3v_4  [CC0402]  64.53 56.87 180 bottom
C255  22u/6.3v_6  [CC0603]  55.21 56.72 180 bottom
C256  *0.1u/10v_4  [CC0402]  89.5 56.67 90 bottom
C257  1u/6.3v_4  [CC0402]  74.46 56.57 0 bottom
C258  0.1u/10v_4  [CC0402]  103.85 56.54 180 bottom
C259  1u/6.3v_4  [CC0402]  66.58 56.19 270 bottom
C260  1u/6.3v_4  [CC0402]  50.56 56.85 270 bottom
C261  *0.1u/10v_4  [CC0402]  92.17 56.03 180 bottom
C262  1u/6.3v_4  [CC0402]  71.16 55.81 90 bottom
C263  1u/6.3v_4  [CC0402]  72.68 55.81 90 bottom
C264  1u/6.3v_4  [CC0402]  69.51 55.17 90 bottom
C265  1u/6.3v_4  [CC0402]  80.68 55.04 270 bottom
C266  1u/6.3v_4  [CC0402]  49.55 56.82 270 bottom
C267  0.1u/10v_4  [CC0402]  67.98 54.66 270 bottom
C268  0.1u/10v_4  [CC0402]  100.8 54.51 270 bottom
C270  0.1u/10v_4  [CC0402]  63.87 53.04 90 bottom
C271  2.2u/6.3v_6  [CC0603]  60.42 52.6 180 bottom
C272  em@0.1u/10v_4  [CC0402]  112.8 23.84 0 bottom
C273  0.1u/10v_4  [CC0402]  67.1 50.47 0 bottom
C274  *0.1u/10v_4  [CC0402]  139.92 49.81 180 bottom
C275  em@0.1u/10v_4  [CC0402]  112.71 21.13 0 bottom
C276  em@0.1u/10v_4  [CC0402]  90.77 18.38 180 bottom
C277  2.2u/6.3v_6  [CC0603]  62.07 44.86 0 bottom
C278  em@1u/6.3v_4  [CC0402]  112.71 18.84 180 bottom
C279  em@1u/6.3v_4  [CC0402]  112.71 22.27 180 bottom
C282  1u/10v_6  [CC0603]  136.49 43.97 90 bottom
C284  10u/6.3v_6  [CC0603]  141.85 42.93 270 bottom
C288  *.1u/16v_4  [CC0402]  145.76 40.79 180 bottom
C290  4.7u/6.3v_6  [CC0603]  141.44 41.05 180 bottom
C292  2.2u/6.3v_6  [CC0603]  67.85 37.61 180 bottom
C293  2.2u/6.3v_6  [CC0603]  73.82 37.61 180 bottom
C294  0.1u/10v_4  [CC0402]  78.39 37.61 180 bottom
C295  1u/6.3v_4  [CC0402]  83.21 37.61 0 bottom
C296  39p/50v_4  [CC0402]  123.79 37.24 0 bottom
C298  10u/6.3v_6  [CC0603]  67.85 35.96 0 bottom
C299  10u/6.3v_6  [CC0603]  73.82 35.96 0 bottom
C300  10u/6.3v_6  [CC0603]  78.39 35.96 180 bottom
C301  10u/6.3v_6  [CC0603]  83.21 35.96 180 bottom
C302  0.1u/10v_4  [CC0402]  108.22 35.59 90 bottom
C303  10u/6.3v_6  [CC0603]  43.11 34.87 0 bottom
C304  0.1u/10v_4  [CC0402]  75.72 34.82 180 bottom
C305  *2.2u/6.3v_6  [CC0603]  106.46 34.82 90 bottom
C307  1u/6.3v_4  [CC0402]  43.11 33.73 0 bottom
C308  0.1u/10v_4  [CC0402]  67.85 33.8 0 bottom
C309  0.1u/10v_4  [CC0402]  72.42 33.8 0 bottom
C310  0.1u/10v_4  [CC0402]  83.34 33.8 180 bottom
C311  1u/6.3v_4  [CC0402]  43.11 32.71 0 bottom
C314  0.1u/10v_4  [CC0402]  46.51 31.9 180 bottom
C315  0.1u/10v_4  [CC0402]  46.51 30.75 180 bottom
C316  1u/6.3v_4  [CC0402]  42.96 29.1 0 bottom
C317  1u/6.3v_4  [CC0402]  42.96 28.09 0 bottom
C318  0.1u/10v_4  [CC0402]  66.39 27.2 0 bottom
C319  0.1u/10v_4  [CC0402]  75.47 26.99 180 bottom
C320  0.1u/10v_4  [CC0402]  77.5 26.99 0 bottom
C321  *0.1u/10v_4  [CC0402]  102.96 33.05 180 bottom
C322  0.1u/10v_4  [CC0402]  72.17 26.69 0 bottom
C323  0.1u/10v_4  [CC0402]  80.8 26.69 180 bottom
C324  10u/6.3v_6  [CC0603]  68.48 26.31 90 bottom
C325  10u/6.3v_6  [CC0603]  84.48 26.31 90 bottom
C326  10u/6.3v_6  [CC0603]  79.15 26.11 90 bottom
C327  10u/6.3v_6  [CC0603]  73.82 25.93 90 bottom
C328  *2.2u/6.3v_6  [CC0603]  66.13 25.93 0 bottom
C329  *10p/50v_4  [CC0402]  52.04 18.06 180 bottom
C330  *10p/50v_4  [CC0402]  54.07 18.06 0 bottom
C331  0.1u/10v_4  [CC0402]  56.41 15.57 180 bottom
C332  1u/6.3v_4  [CC0402]  38.07 10.44 90 bottom
C333  *1000p/50v_4  [CC0402]  82.13 8.53 90 bottom
C335  1u/6.3v_4  [CC0402]  36.03 8.15 90 bottom
C336  1u/6.3v_4  [CC0402]  38.07 8.15 270 bottom
C337  330p/50v_4  [CC0402]  31.84 80.42 270 top
C338  0.1u/25v_4  [CC0402]  47.21 19.66 180 bottom
C339  0.1u/25v_4  [CC0402]  47.21 20.75 180 bottom
C340  hd@10u/6.3v_6  [CC0603]  162.78 37.62 90 bottom
C341  hd@0.01u/25v_4  [CC0402]  162.27 39.65 0 bottom
C342  *22p/50v_4  [CC0402]  12.01 66.12 180 top
C343  0.1u/10v_4  [CC0402]  15.56 68.15 270 top
C344  1u/10v_6  [CC0603]  13.61 73.69 270 top
C345  1u/10v_6  [CC0603]  13.78 70.43 270 top
C347  *1000p/50v_4  [CC0402]  12.01 69.55 0 top
C348  4.7u/6.3v_6  [CC0603]  19.4 83.34 0 top
C349  4.7u/6.3v_6  [CC0603]  19.4 82.07 0 top
C350  2.2n/50v_6  [CC0603]  156.66 18.75 270 top
C351  *0.1u/25v_4  [CC0402]  83.25 8.46 270 bottom
C355  tpm@10u/6.3v_6  [CC0603]  51.44 40.51 180 top
C356  tpm@0.1u/10v_4  [CC0402]  41.58 38.2 0 top
C357  tpm@10u/6.3v_6  [CC0603]  39.97 37.52 270 top
C358  *10p/50v_4  [CC0402]  58.06 14.17 270 bottom
C359  *0.1u/10v_4  [CC0402]  133.44 42.93 0 bottom
CN4  sd-card  [SDCARD-CS1S-441-H-N-11P]  14.1 41 270 top
CN6  usb3.0 conn  [USB-53063-00902-001-9P-SMT]  89.1 99.63 180 top
CN7  hdmi conn  [HDMI-HDM-19DVXB-19P]  65.4 99.48 180 top
CN8  usb_con  [USB-020133GR004M22BZL-4P]  107.05 99.15 180 top
CN9  rj45  [RJ45-C100MP-10809-L-8P]  133.3 93.5 180 top
CN10  wlan conn  [MINIPCI-80053-1023-52P-SMT]  165.45 86.7 90 top
CN11  2sj2372-108111f  [PHJK-2SJ3072-108111F-6P]  2.7 81.5 270 top
CN14  hd@hdd conn  [SATA-C166KN-12209-L-22P-L-SMT]  164.5 39.3 90 top
CN15  rtc_socket  [ML1220-SMT]  22.19 15.52 90 top
CN16  lvds  [MSC-RB30-5-FG-30P-L-SMT]  35.35 69.09 0 bottom
CN17  kb conn  [85208-24071-24P-L]  136.57 27.15 180 bottom
CN18  tp_cn  [88513-0801-8P-L]  48.24 15.95 180 bottom
CN19  power conn  [88266-040XX-XXX-4P-L]  14.6 7.23 180 bottom
CP6  *220p_8p4r  [8P4R]  141.32 33.55 180 bottom
CP7  *220p_8p4r  [8P4R]  145 33.55 180 bottom
CP8  *220p_8p4r  [8P4R]  126.84 33.43 180 bottom
CP9  *220p_8p4r  [8P4R]  130.52 33.43 180 bottom
CP10  *220p_8p4r  [8P4R]  134.2 33.43 180 bottom
CP11  *220p_8p4r  [8P4R]  137.63 33.43 180 bottom
D6  *az5125-01j  [RC0402]  62.45 90.16 180 top
D7  *5v/30v/0.2p_4  [CC0402]  106.26 88.29 0 top
D8  *5v/30v/0.2p_4  [CC0402]  108.42 88.29 180 top
D9  rb500v-40  [DSM]  62.7 85.12 180 top
D10  rb500v-40  [DSM]  58.39 84.86 0 top
D11  *rclamp0531t  [RC0402]  14.67 80.29 0 top
D14  *rclamp0531t  [RC0402]  8.83 76.28 180 top
D15  *5.5v/25v/410p_4  [CC0402]  44.11 80.57 180 top
D16  rb500v-40  [DSM]  42.1 78.16 270 top
D17  *rclamp0531t  [RC0402]  10.86 76.28 0 top
D18  *rclamp0531t  [RC0402]  17.34 78.26 90 top
D19  rb500v-40  [DSM]  40.33 78.16 270 top
D20  *rclamp0531t  [RC0402]  14.67 82.37 0 top
D24  *rb500v-40  [DSM]  126.33 50.19 90 top
D31  bas316  [DSM]  32.71 68.68 270 top
D32  bas316  [DSM]  36.01 67.39 180 top
D33  *vport_6  [RC0603]  148.81 82.37 180 bottom
D34  *vport_6  [RC0603]  148.81 81.15 180 bottom
D35  rb500v-40  [DSM]  130.52 44.09 270 bottom
D36  bat54c  [SOT323_213-2_1-1_3-2N7002W]  33.49 8.92 180 bottom
D37  *rclamp0531t  [RC0402]  30.83 80.42 270 top
G6  *short_ pad1  [SOLDERJUMPER-2]  33.24 12.34 180 bottom
G7  *short_ pad1  [SOLDERJUMPER-2]  36.29 4.78 270 bottom
HOLE7  *o-zhj-9  [O-ZHJ-9]  119.1 93 0 top
HOLE8  *hg-tc276bc335d118p2  [HG-TC276BC335D118P2]  50.4 92 0 top
HOLE9  *o-zhj-21  [O-ZHJ-21]  7.5 90.1 0 top
HOLE10  h-c197d142p2  [H-C197D140P2]  19.6 64.5 0 top
HOLE11  h-c197d142p2  [H-C197D140P2]  88.22 72.15 0 top
HOLE12  *hg-tc394bc236d118p2  [HG-TC394BC236D118P2]  157.31 59.5 0 top
HOLE13  h-c197d142p2  [H-C197D140P2]  50.91 48.83 0 top
HOLE14  *hg-c492d335p2  [HG-C492D335P2]  3.5 15.5 0 top
HOLE15  *hg-tc256bc354d118p2  [HG-TC256BC354D118P2]  162.1 4.5 0 top
HOLE16  *hg-tc256bc354d118p2  [HG-TC256BC354D118P2]  117.1 4.5 0 top
HOLE17  *h-tc197bc83d83pt  [H-TC197BC83D83PT]  165.21 61.3 180 bottom
HOLE18  *h-tc197bc83d83pt  [H-TC197BC83D83PT]  165.21 17.3 180 bottom
HOLE19  *hg-tc315bc276d118p2  [HG-TC315BC276D118P2]  29.6 3 0 top
HOLE20  *h-o39x475d39x475n  [H-O39X475D39X475N]  167.1 8.74 0 top
HOLE21  *h-o39x279d39x279n  [H-O39X279D39X279N]  167.2 66.76 0 top
HOLE22  *h-c236d118p2  [H-C236D118P2]  5 68.9 0 top
HOLE23  *h-c51d51n  [H-C51D51N]  14.1 52.2 0 top
HOLE24  *h-c70d70n  [H-C70D70N]  14.1 30.2 0 top
JDIM6  ddr3-dimm0_h=4.0_std  [DDR-DDRSK-20401-TP4B-204P-SMT]  76.01 30.5 180 top
L1  blm15pd121sn1d  [RC0402]  72.76 81.18 0 top
L7  mcm2012b900gbe/400ma/90ohm  [CHOKE-DLW21S-4P]  107.28 86.13 270 top
L10  hcb1608kf_1.5a_6  [RC0603]  33.7 80.72 0 top
L13  4.7uh_8  [L3_2X2_5-3_2]  150.97 69.62 90 top
L14  pby160808t-250y-n/3a/25ohm_6  [RC0603]  137.63 50.7 0 top
L18  pby160808t-250y-n/3a/25ohm_6  [RC0603]  141.44 39.78 0 bottom
LED6  battery led  [LED19-123-Y2ST1D-C30-2T-4P]  54.05 96.7 270 top
LED7  battery led  [LED19-123-Y2ST1D-C30-2T-4P]  76.45 96.7 270 top
MR6  och1691wad  [SOT23_123-2_8-1_9]  140.61 87.05 90 top
NOREF  -  [unnamed]  157.32 9.17 0 top
NOREF#2  -  [#2]  99.36 41.43 0 top
NOREF#3  -  [unnamed]  7.97 3.96 0 top
NOREF#4  -  [#2]  76.93 -20.04 0 top
NOREF#5  -  [#2]  26.13 -65.25 0 top
NOREF#6  -  [unnamed]  156.07 85.37 0 top
NOREF#7  -  [unnamed]  7.97 3.96 180 bottom
NOREF#8  -  [unnamed]  6.16 82.07 180 bottom
NOREF#9  -  [#2]  94.35 37.97 180 bottom
NOREF#10  -  [unnamed]  157.32 9.17 180 bottom
PC6  33u/25v_6x4.5  [ECAP6_3X6_1-7_2]  122.72 84.53 270 top
PC7  330u/2v_7343  [CC7343]  100.17 81.31 90 top
PC8  10u/6.3v_8  [CC0805]  101.69 80.8 270 bottom
PC9  0.1u/10v_4  [CC0402]  103.6 80.92 270 top
PC10  2200p/50v_4  [CC0402]  119.6 79.65 270 top
PC12  0.1u/50v_6  [CC0603]  120.74 79.4 270 top
PC13  4.7u/25v_8  [CC0805]  122.39 79.02 90 top
PC14  330u/2v_7343  [CC7343]  100.17 71.78 90 top
PC15  0.1u/50v_6  [CC0603]  120.74 69.11 90 top
PC16  220p/50v_4  [CC0402]  126.72 68.99 0 top
PC17  2200p/50v_4  [CC0402]  119.61 68.76 90 top
PC18  330p/50v_4  [CC0402]  128.11 67.08 90 top
PC19  1u/10v_6  [CC0603]  124.87 65.46 180 top
PC20  330p/50v_4  [CC0402]  127.22 63.27 270 top
PC21  *10u/6.3v_6  [CC0603]  45.81 60.6 270 top
PC22  10u/6.3v_6  [CC0603]  31.21 60.48 180 top
PC23  0.1u/10v_4  [CC0402]  47.08 60.48 270 top
PC24  0.01u/50v_4  [CC0402]  28.92 58.01 0 top
PC25  1u/6.3v_4  [CC0402]  31.72 57.94 0 top
PC26  *68p/50v_4  [CC0402]  114.65 57.68 90 top
PC27  1u/6.3v_4  [CC0402]  113.6 57.67 90 top
PC28  0.01u/50v_4  [CC0402]  109.82 56.54 90 top
PC29  *68p/50v_4  [CC0402]  33.27 56.92 270 top
PC30  *22p/50v_4  [CC0402]  116.3 55.52 180 top
PC31  10u/6.3v_6  [CC0603]  110.94 55.39 90 top
PC32  0.1u/25v_4  [CC0402]  124.43 55.14 180 top
PC33  0.1u/10v_4  [CC0402]  104.11 48.62 180 top
PC34  *2200p/50v_4  [CC0402]  109.82 54.38 90 top
PC35  22u/6.3v_6  [CC0603]  103.98 47.4 0 top
PC36  *0.1u/10v_4  [CC0402]  32.86 54.64 90 top
PC37  22u/6.3v_6  [CC0603]  35.22 53.49 0 top
PC38  0.1u/10v_4  [CC0402]  116.3 52.48 0 top
PC39  *2200p/50v_4  [CC0402]  33.37 52.22 0 top
PC40  0.1u/10v_4  [CC0402]  35.53 52.22 180 top
PC41  0.1u/25v_4  [CC0402]  118.99 50.11 180 top
PC42  2200p/50v_4  [CC0402]  118.99 48.97 180 top
PC43  *0.1u/10v_4  [CC0402]  122.83 47.98 0 top
PC44  10u/6.3v_6  [CC0603]  115.41 46.51 90 top
PC45  22u/6.3v_6  [CC0603]  158.72 38.38 180 top
PC46  0.1u/10v_4  [CC0402]  158.64 43.43 180 top
PC47  1u/6.3v_4  [CC0402]  123.29 45.93 0 top
PC48  *0.1u/10v_4  [CC0402]  114.91 43.49 0 top
PC49  0.1u/25v_4  [CC0402]  123.41 42.19 90 top
PC50  22u/6.3v_6  [CC0603]  114.11 41.33 0 top
PC51  220u/6.3v_6x4.2  [ECAP6_3X6_1-7_2]  157.93 48.84 0 top
PC52  22u/6.3v_6  [CC0603]  114.11 40.16 0 top
PC53  10u/6.3v_6  [CC0603]  32.45 39.34 270 top
PC54  *10u/6.3v_6  [CC0603]  33.8 39.34 270 top
PC55  22u/6.3v_6  [CC0603]  114.11 38.99 0 top
PC56  0.1u/10v_4  [CC0402]  28.79 38.76 90 top
PC57  0.22u/10v_4  [CC0402]  31.08 38.71 90 top
PC58  22u/6.3v_6  [CC0603]  114.11 37.82 0 top
PC59  0.1u/10v_4  [CC0402]  28.13 36.8 0 top
PC60  0.1u/10v_4  [CC0402]  114.14 36.73 0 top
PC61  0.1u/25v_4  [CC0402]  148.94 35.84 180 top
PC62  0.01u/25v_4  [CC0402]  28.13 35.53 0 top
PC63  *0.1u/10v_4  [CC0402]  36.11 35.13 180 top
PC64  22u/6.3v_6  [CC0603]  158.72 39.65 180 top
PC65  22u/6.3v_6  [CC0603]  158.72 40.92 180 top
PC66  22u/6.3v_6  [CC0603]  158.72 42.19 180 top
PC67  *0.1u/10v_4  [CC0402]  35.98 33.99 180 top
PC68  1u/6.3v_4  [CC0402]  148.94 33.55 180 top
PC69  1u/6.3v_4  [CC0402]  28.03 33.05 0 top
PC70  2200p/50v_4  [CC0402]  30.95 32.41 180 top
PC71  0.1u/25v_4  [CC0402]  33.42 32.03 0 top
PC72  0.1u/25v_4  [CC0402]  30.95 31.39 180 top
PC73  2200p/50v_4  [CC0402]  152.82 30.91 0 top
PC74  *220uf/6.3v_6x4.2  [ECAP6_3X6_1-7_2]  119.09 30.84 270 top
PC75  0.1u/25v_4  [CC0402]  152.82 29.9 0 top
PC76  10u/25v_8  [CC0805]  126.71 27.58 180 top
PC77  0.01u/50v_4  [CC0402]  140.3 26.7 270 top
PC78  *2200p/50v_4  [CC0402]  130.14 26.44 180 top
PC79  4.7u/25v_8  [CC0805]  138.65 26.09 270 top
PC80  33u/25v_6x4.5  [ECAP6_3X6_1-7_2]  155.03 25.68 270 top
PC81  10u/25v_8  [CC0805]  126.71 25.55 180 top
PC82  2.2u/10v_4  [CC0402]  133.95 23.52 270 top
PC83  0.47u/25v_6  [CC0603]  132.68 22.89 90 top
PC84  1000p/50v_4  [CC0402]  133.19 19.46 0 top
PC85  0.47u/25v_6  [CC0603]  132.68 17.04 180 top
PC86  0.1u/10v_4  [CC0402]  36.54 16.54 270 top
PC87  0.01u/50v_4  [CC0402]  132.17 15.27 90 top
PC88  47p/50v_4  [CC0402]  134.33 15.27 90 top
PC89  0.047u/25v_4  [CC0402]  140.68 15.27 90 top
PC90  *0.01u/50v_4  [CC0402]  145.89 14.38 0 top
PC91  *0.1u/25v_4  [CC0402]  148.17 14.38 180 top
PC92  330u/2.5v_6x4.2  [ECAP6_3X6_1-7_2]  33.75 11.84 180 top
PC93  0.1u/25v_4  [CC0402]  151.44 81.56 270 bottom
PC94  4.7u/25v_8  [CC0805]  118.96 78.89 90 bottom
PC95  2200p/50v_6  [CC0603]  116.73 76.51 90 bottom
PC96  10u/6.3v_8  [CC0805]  107.03 73.3 270 bottom
PC97  0.1u/10v_4  [CC0402]  102.96 73.05 270 bottom
PC98  *330p/50v_4  [CC0402]  129.39 72.57 90 bottom
PC99  0.1u/25v_4  [CC0402]  130.4 72.57 270 bottom
PC100  *0.1u/25v_4  [CC0402]  131.42 72.57 270 bottom
PC101  2200p/50v_6  [CC0603]  116.17 71.53 270 bottom
PC102  470p/50v_4  [CC0402]  127.36 70.97 180 bottom
PC103  0.1u/10v_4  [CC0402]  135.47 70.89 180 bottom
PC104  33n/25v_4  [CC0402]  133.22 69.78 0 bottom
PC105  1000p/50v_4  [CC0402]  126.85 69.4 90 bottom
PC106  4.7u/25v_8  [CC0805]  117.82 69.37 270 bottom
PC107  4.7u/25v_8  [CC0805]  119.85 69.37 270 bottom
PC108  4700p/25v_4  [CC0402]  130.39 69.37 270 bottom
PC109  *0.01u/50v_4  [CC0402]  128.9 69.34 270 bottom
PC110  47n/16v_4  [CC0402]  133.22 68.76 0 bottom
PC111  0.22u/25v_6  [CC0603]  122.66 66.93 180 bottom
PC112  2200p/50v_4  [CC0402]  113.38 65.56 0 bottom
PC113  1u/10v_4  [CC0402]  123.33 65.43 0 bottom
PC114  *10u/6.3v_6  [CC0603]  106.26 64.8 90 bottom
PC115  0.1u/10v_4  [CC0402]  107.53 64.54 90 bottom
PC116  0.1u/10v_4  [CC0402]  113.38 64.16 0 bottom
PC117  0.22u/25v_6  [CC0603]  122.78 63.68 180 bottom
PC118  43p/50v_4  [CC0402]  131.66 63.55 0 bottom
PC119  2200p/50v_4  [CC0402]  40.73 56.54 270 bottom
PC120  0.1u/10v_4  [CC0402]  117.31 62.64 270 bottom
PC121  0.1u/10v_4  [CC0402]  107.53 62.26 270 bottom
PC122  *10u/6.3v_6  [CC0603]  106.14 62.13 270 bottom
PC123  4700p/25v_4  [CC0402]  128.49 61.37 270 bottom
PC124  47n/16v_4  [CC0402]  129.51 61.37 90 bottom
PC125  33n/25v_4  [CC0402]  130.52 61.37 90 bottom
PC126  *0.1u/25v_4  [CC0402]  132.05 61.37 180 bottom
PC127  *10u/6.3v_6  [CC0603]  120.11 61.24 0 bottom
PC128  220p/50v_4  [CC0402]  125.16 61.16 0 bottom
PC129  0.1u/10v_4  [CC0402]  46.04 61.09 0 bottom
PC130  *10u/6.3v_6  [CC0603]  116.17 60.99 0 bottom
PC131  2200p/50v_4  [CC0402]  118.08 60.48 270 bottom
PC132  0.1u/10v_4  [CC0402]  113 60.22 270 bottom
PC133  2200p/50v_4  [CC0402]  114.14 60.22 270 bottom
PC134  0.1u/25v_4  [CC0402]  132.05 60.22 180 bottom
PC135  0.1u/10v_4  [CC0402]  119.98 59.97 0 bottom
PC136  1000p/50v_4  [CC0402]  124.18 59.62 270 bottom
PC137  *0.01u/50v_4  [CC0402]  126.21 59.62 90 bottom
PC138  *22p/50v_4  [CC0402]  31.72 58.95 0 bottom
PC139  0.1u/10v_4  [CC0402]  47.9 56.9 180 bottom
PC140  *330p/50v_4  [CC0402]  128.49 57.68 180 bottom
PC141  470p/50v_4  [CC0402]  125.83 57.2 270 bottom
PC142  0.1u/10v_4  [CC0402]  46.02 59.69 0 bottom
PC143  0.1u/10v_4  [CC0402]  35.27 56.54 270 bottom
PC145  0.1u/10v_4  [CC0402]  112.84 55.52 180 bottom
PC146  0.1u/10v_4  [CC0402]  120.23 54.25 0 bottom
PC147  0.1u/10v_4  [CC0402]  42.92 53.19 90 bottom
PC148  10u/6.3v_6  [CC0603]  44.42 53.14 270 bottom
PC149  *10u/6.3v_6  [CC0603]  45.69 53.14 270 bottom
PC150  4.7u/25v_8  [CC0805]  118.2 51.46 0 bottom
PC151  4.7u/6.3v_6  [CC0603]  44.03 50.06 180 bottom
PC152  0.1u/10v_4  [CC0402]  146.14 49.94 90 bottom
PC153  4.7u/25v_8  [CC0805]  118.2 49.3 0 bottom
PC154  *2200p/50v_4  [CC0402]  117.57 46.63 90 bottom
PC155  0.47uf/4v_4  [CC0402]  40.58 46 0 bottom
PC156  *10u/6.3v_6  [CC0603]  33.09 41.4 180 top
PC157  0.1u/10v_4  [CC0402]  58.06 46.41 180 bottom
PC158  0.1u/10v_4  [CC0402]  59.53 45.36 180 bottom
PC159  1u/6.3v_4  [CC0402]  26.13 45.11 270 bottom
PC160  0.1u/25v_4  [CC0402]  153.56 29.79 180 bottom
PC161  *10u/6.3v_6  [CC0603]  35.55 44.76 270 bottom
PC162  10u/6.3v_6  [CC0603]  36.82 44.76 270 bottom
PC163  2200p/50v_4  [CC0402]  47.44 45.34 270 bottom
PC164  0.1u/10v_4  [CC0402]  53.56 44.22 90 bottom
PC165  0.1u/10v_4  [CC0402]  21.43 43.84 270 bottom
PC166  *10u/6.3v_6  [CC0603]  52.29 43.84 90 bottom
PC167  0.1u/10v_4  [CC0402]  36.03 42.93 0 bottom
PC168  0.1u/10v_4  [CC0402]  26.13 42.7 90 bottom
PC169  0.1u/10v_4  [CC0402]  47.44 42.71 90 bottom
PC170  10u/6.3v_6  [CC0603]  24.22 42.06 0 bottom
PC171  2200p/50v_4  [CC0402]  53.81 41.55 90 bottom
PC172  2200p/50v_4  [CC0402]  54.96 41.55 90 bottom
PC173  0.1u/10v_4  [CC0402]  25.42 40.95 180 bottom
PC174  *2200p/50v_4  [CC0402]  155.21 37.82 270 bottom
PC175  4.7u/25v_8  [CC0805]  153.81 35.51 180 bottom
PC176  *0.1u/10v_4  [CC0402]  149.61 35.44 90 bottom
PC177  4.7u/25v_8  [CC0805]  153.81 33.5 180 bottom
PC178  0.1u/10v_4  [CC0402]  161.38 30.63 0 bottom
PC179  4.7u/25v_8  [CC0805]  32.68 29.97 0 bottom
PC180  4.7u/25v_8  [CC0805]  32.68 27.97 0 bottom
PC181  *2200p/50v_4  [CC0402]  30.47 27.18 90 bottom
PC182  2200p/50v_4  [CC0402]  157.45 26.57 270 bottom
PC183  0.1u/50v_6  [CC0603]  43.53 25.81 0 bottom
PC184  0.1u/10v_4  [CC0402]  159.22 23.39 0 bottom
PC185  *10u/6.3v_6  [CC0603]  158.97 22.12 0 bottom
PC186  0.1u/25v_4  [CC0402]  34.38 20.6 0 bottom
PC187  0.47u/25v_6  [CC0603]  84.93 17.55 0 bottom
PC188  0.1u/50v_6  [CC0603]  41.34 17.6 270 bottom
PC189  1u/16v_4  [CC0402]  81.37 17.42 180 bottom
PC190  *47p/50v_4  [CC0402]  70.58 16.79 180 bottom
PC191  *47p/50v_4  [CC0402]  74.13 18.44 270 bottom
PC192  1u/35v_6  [CC0603]  84.93 16.28 180 bottom
PC193  0.1u/25v_4  [CC0402]  63.21 15.65 0 bottom
PC194  100p/50v_4  [CC0402]  65.24 15.65 180 bottom
PC195  0.1u/25v_4  [CC0402]  84.17 14.5 90 bottom
PC196  0.1u/25v_4  [CC0402]  84.3 12.8 0 bottom
PC197  0.1u/10v_4  [CC0402]  82.26 10.95 90 bottom
PC198  2.2u/6.3v_4  [CC0402]  36.9 43.43 90 top
PC199  4.7u/10v_6  [CC0603]  27.7 38.68 270 top
PC200  0.1u/10v_4  [CC0402]  18.05 41.55 90 bottom
PC201  0.1u/10v_4  [CC0402]  14.98 43.18 180 bottom
PC202  0.1u/10v_4  [CC0402]  14.88 35.89 0 bottom
PC203  *10u/6.3v_6  [CC0603]  15.99 37.14 180 bottom
PC204  0.1u/10v_4  [CC0402]  16.93 35.76 180 bottom
PC205  *10u/6.3v_6  [CC0603]  15.33 44.4 180 bottom
PD6  p4smaj20a  [D-DO-214AC]  153.21 81.63 270 top
PD7  1n4148ws  [DSM]  133.82 25.55 0 top
PD8  mew316  [DSM]  125.95 16.79 180 top
PD9  mew316  [DSM]  125.95 14.76 180 top
PD10  da2j10100l  [DSM]  38.47 28.09 180 bottom
PD11  pdz5.6b  [DSM]  75.66 17.42 90 bottom
PD12  pdz5.6b  [DSM]  72.61 17.42 90 bottom
PJ6  power_jack  [DCJK-2DC2003-000111-3P-V]  152.75 98.85 180 top
PJ7  c114f3-108a1-l_batt_conn  [50458-00801-V02-8P-L]  69.56 7.67 173.5 bottom
PL6  0.47uh_7x7x3  [CHOKE-PCMC063T-R82MN-4P-SMT]  108.93 78.54 180 top
PL7  0.47uh_7x7x3  [CHOKE-PCMC063T-R82MN-4P-SMT]  108.93 71.43 180 top
PL8  1uh_7x7x3  [CHOKE-PCMC063T-3R3MN-SMT]  110.07 48.41 180 top
PL9  1uh_7x7x3  [CHOKE-PCMC063T-3R3MN-SMT]  32.73 48.08 0 top
PL10  3.3uh_7x7x3  [CHOKE-PCMC063T-3R3MN-SMT]  151.35 41.17 90 top
PL11  3.3uh_7x7x3  [CHOKE-PCMC063T-3R3MN-SMT]  119.47 39.01 270 top
PL12  6.8uh_7x7x3  [CHOKE-PCMC063T-3R3MN-SMT]  127.35 21.11 0 top
PL13  2.2uh_7x7x3  [CHOKE-PCMC063T-3R3MN-SMT]  33.75 21.23 270 top
PL14  2.2uh/1.85a_2.5x2x1.2  [L3_2X2_5-1_55]  40.24 53.14 0 bottom
PQ2  ao3415  [SOT23_213-3_3-2]  23.56 40.21 0 top
PQ6  aon6978(30v,20a,2.3w)  [POWER-5X6-1_27-7P]  116.3 79.4 90 top
PQ7  aon6978(30v,20a,2.3w)  [POWER-5X6-1_27-7P]  116.31 70.16 270 top
PQ8  mdv1595s  [WDFN5-3_05X3_05-65]  30.32 28.35 90 top
PQ9  mdv1528  [WDFN5-3_05X3_05-65]  34.89 28.22 270 top
PQ10  qm3016d  [TO252_134-9_9-4_57-SMT]  152.11 18.57 180 top
PQ11  ao3404  [SOT23_213-3_3-2]  110.19 64.39 180 bottom
PQ12  2n7002k  [SOT23_213-3_3-2]  39.34 63.04 180 bottom
PQ13  ao3404  [SOT23_213-3_3-2]  110.46 60.6 180 bottom
PQ14  ao3404  [SOT23_213-3_3-2]  43.07 60.99 180 bottom
PQ15  2n7002k  [SOT23_213-3_3-2]  39.08 59.44 180 bottom
PQ16  mdv1528q  [WDFN5-3_05X3_05-65]  120.87 57.05 0 bottom
PQ17  ao3404  [SOT23_213-3_3-2]  115.66 56.92 90 bottom
PQ18  2n7002k  [SOT23_213-3_3-2]  27.78 56.79 180 bottom
PQ20  dtc144eua  [UMT_213-3-1_3]  38.4 56.31 180 bottom
PQ21  2n7002k  [SOT23_213-3_3-2]  140.55 54.25 90 bottom
PQ22  2n7002k  [SOT23_213-3_3-2]  144.11 54.25 90 bottom
PQ23  2n7002k  [SOT23_213-3_3-2]  26.46 53.24 180 bottom
PQ24  dtc144eua  [UMT_213-3-1_3]  147.41 52.86 90 bottom
PQ25  *2n7002k  [SOT23_213-3_3-2]  128.11 52.22 180 bottom
PQ26  *2n7002k  [SOT23_213-3_3-2]  127.6 48.41 90 bottom
PQ27  dtc144eua  [UMT_213-3-1_3]  23.82 44.04 180 bottom
PQ28  ao3404  [SOT23_213-3_3-2]  49.75 43.33 90 bottom
PQ29  ao3404  [SOT23_213-3_3-2]  16.3 33.43 180 bottom
PQ30  ao3404  [SOT23_213-3_3-2]  15.61 40.77 180 bottom
PQ31  ao3404  [SOT23_213-3_3-2]  19.47 38.66 180 bottom
PQ33  dtc144eua  [UMT_213-3-1_3]  45.81 27.76 0 bottom
PQ34  mdv1528q  [WDFN5-3_05X3_05-65]  160.24 27.71 270 bottom
PQ35  ao3409  [SOT23_213-3_3-2]  46.57 23.27 90 bottom
PQ36  2n7002k  [SOT23_213-3_3-2]  43.78 18.82 90 bottom
PQ37  2n7002k  [SOT23_213-3_3-2]  95.57 52.27 90 top
PQ38  ao3404  [SOT23_213-3_3-2]  28.69 41.94 270 top
PR6  470k_4 ntc  [RC0402]  112.74 83.34 90 top
PR7  27.4k/f_4  [RC0402]  111.73 83.34 90 top
PR8  3.83k/f_4  [RC0402]  109.9 83.34 270 top
PR9  10k/f_4_4250ntc  [RC0402]  108.17 82.96 180 top
PR10  2k/f_4  [RC0402]  126.58 70.03 0 top
PR11  *0/short_6  [SHORT0603]  122.15 68.76 270 top
PR12  1/f_6  [RC0603]  123.42 68.76 90 top
PR13  10k/f_4_4250ntc  [RC0402]  108.86 67.34 180 top
PR14  21k/f_4  [RC0402]  127.09 67.08 270 top
PR15  470k_4 ntc  [RC0402]  113.33 65.79 180 top
PR16  27.4k/f_4  [RC0402]  113.33 64.64 180 top
PR17  3.83k/f_4  [RC0402]  113.33 63.63 0 top
PR18  64.9k/f_4  [RC0402]  126.2 63.27 270 top
PR19  2.61k/f_4  [RC0402]  128.24 61.75 90 top
PR20  11k/f_4  [RC0402]  129.25 61.75 90 top
PR21  2k/f_4  [RC0402]  125.82 60.73 0 top
PR22  *0/short_8  [SHORT0805]  28.03 59.59 0 top
PR23  *0/short_8  [SHORT0805]  112.11 59.59 180 top
PR24  10_6  [RC0603]  31.21 59.21 180 top
PR25  10_6  [RC0603]  111.78 57.68 180 top
PR26  *0/short_4  [SHORT0402]  116.3 57.68 180 top
PR27  20k/f_4  [RC0402]  116.3 56.54 0 top
PR29  10k/f_4  [RC0402]  116.3 54.51 180 top
PR32  20k/f_4  [RC0402]  116.3 53.49 0 top
PR33  *2.2_6  [RC0603]  110.3 52.73 0 top
PR34  *2.2_6  [RC0603]  30.95 52.07 180 top
PR35  *0/short_4  [SHORT0402]  118.08 51.46 180 top
PR36  10k/f_4  [RC0402]  115.41 49.43 90 top
PR37  *330k/f_4  [RC0402]  124.55 48.54 270 top
PR38  *0/short_4  [SHORT0402]  116.55 47.02 270 top
PR39  *665k/f_4  [RC0402]  123.29 46.94 0 top
PR40  1/f_6  [RC0603]  123.24 44.58 180 top
PR41  10k/f_4  [RC0402]  114.91 44.5 180 top
PR42  *0/short_4  [SHORT0402]  114.91 42.47 180 top
PR43  100/j_4  [RC0402]  30.06 38.71 90 top
PR44  *0/short_4  [SHORT0402]  35.98 38.23 180 top
PR45  47k/f_4  [RC0402]  35.98 37.16 0 top
PR46  120k/f_4  [RC0402]  35.98 36.14 0 top
PR47  1/f_6  [RC0603]  149.17 34.65 0 top
PR48  31.6k/f_4  [RC0402]  28.13 34.52 0 top
PR49  *0/short_4  [SHORT0402]  156.51 34.29 180 top
PR50  *0/short_4  [SHORT0402]  156.51 33.25 180 top
PR51  2.2_6  [RC0603]  35.78 32.79 0 top
PR52  82k/f_4  [RC0402]  148.43 31.36 270 top
PR53  11k/f_4  [RC0402]  149.44 31.36 90 top
PR54  *0/short_6  [SHORT0603]  136.87 26.19 270 top
PR55  rc1206-r020  [F3_2X1_65-2_8]  120.11 25.68 180 top
PR56  *2.2_6  [RC0603]  129.76 25.17 180 top
PR57  *0/short_4  [SHORT0402]  119.98 22 90 top
PR58  *0/short_4  [SHORT0402]  121.12 22 90 top
PR59  100k/f_4  [RC0402]  133.19 18.31 0 top
PR60  84.5k/f_4  [RC0402]  129.89 16.92 0 top
PR61  560k/f_4  [RC0402]  129.89 15.77 180 top
PR62  *0/short_6  [SHORT0603]  137.51 15.52 270 top
PR63  10/f_4  [RC0402]  133.32 15.27 270 top
PR64  100k/f_4  [RC0402]  135.35 15.27 90 top
PR65  *0_4  [RC0402]  136.36 15.27 270 top
PR66  *0/short_4  [SHORT0402]  138.65 15.27 90 top
PR67  *0/short_4  [SHORT0402]  139.67 15.27 90 top
PR68  *0/short_4  [SHORT0402]  141.7 15.27 90 top
PR69  20/f_6  [RC0603]  130.01 14.38 180 top
PR70  *0/short_4  [SHORT0402]  143.48 14.38 180 top
PR71  rc1206-r020  [F3_2X1_65-2_8]  153.6 83.85 0 bottom
PR72  *0/short_4  [SHORT0402]  153.09 81.56 90 bottom
PR73  *0/short_4  [SHORT0402]  154.23 81.56 90 bottom
PR74  3.65k/f_6  [RC0603]  109.82 80.54 270 bottom
PR75  1/f_4  [RC0402]  107.8 80.01 270 bottom
PR76  *10_4  [RC0402]  59.78 77.62 0 bottom
PR77  2.2_6  [RC0603]  114.19 77.17 180 bottom
PR78  *0/short_4  [SHORT0402]  59.91 76.1 90 bottom
PR79  1.91k/f_4  [RC0402]  126.34 72.57 90 bottom
PR80  499/f_4  [RC0402]  127.36 73.21 90 bottom
PR81  1.78k/f_4  [RC0402]  128.37 72.57 270 bottom
PR82  2.61k/f_4  [RC0402]  132.44 72.57 270 bottom
PR83  649/f_4  [RC0402]  131.29 70.92 180 bottom
PR84  11k/f_4  [RC0402]  133.33 70.92 0 bottom
PR85  2.2_6  [RC0603]  115.41 68.94 180 bottom
PR86  *0/short_4  [SHORT0402]  125.83 69.4 270 bottom
PR87  21k/f_4  [RC0402]  127.86 69.4 90 bottom
PR88  787/f_4  [RC0402]  131.66 69.37 270 bottom
PR89  1/f_4  [RC0402]  107.8 69.29 90 bottom
PR90  *100k/f_4  [RC0402]  135.99 69.27 180 bottom
PR91  3.65k/f_6  [RC0603]  110.08 69.01 90 bottom
PR92  2.2/f_6  [RC0603]  122.66 68.76 0 bottom
PR93  *0/short_4  [SHORT0402]  135.98 68.22 0 bottom
PR95  20/f_4  [RC0402]  132.68 67.08 180 bottom
PR96  73.2/f_4  [RC0402]  134.36 66.5 90 bottom
PR97  *0/short_4  [SHORT0402]  132.68 65.94 180 bottom
PR98  16.9/f_4  [RC0402]  131.66 64.8 180 bottom
PR99  *73.2/f_4  [RC0402]  133.7 64.8 0 bottom
PR100  *0/short_4  [SHORT0402]  89.88 64.41 0 bottom
PR101  22_8  [RC0805]  42.92 63.83 0 bottom
PR102  *10_4  [RC0402]  91.91 64.03 180 bottom
PR103  1m_6  [RC0603]  41.85 56.19 270 bottom
PR104  73.2/f_4  [RC0402]  133.7 63.53 0 bottom
PR105  *0/short_4  [SHORT0402]  89.88 63.02 0 bottom
PR106  *10_4  [RC0402]  91.91 63.02 0 bottom
PR107  *0/short_4  [SHORT0402]  132.05 62.51 180 bottom
PR108  *499/f_4  [RC0402]  135.42 62.81 90 bottom
PR109  2.2/f_6  [RC0603]  122.78 62.28 0 bottom
PR110  *0/short_4  [SHORT0402]  89.88 62 0 bottom
PR111  *10_4  [RC0402]  91.91 62 180 bottom
PR112  1.91k/f_4  [RC0402]  123.17 60.63 270 bottom
PR113  1m_6  [RC0603]  29.96 59.82 90 bottom
PR114  *0/short_4  [SHORT0402]  31.74 59.97 0 bottom
PR115  21k/f_4  [RC0402]  125.2 59.62 270 bottom
PR116  787/f_4  [RC0402]  127.36 59.24 270 bottom
PR117  649/f_4  [RC0402]  128.37 59.24 270 bottom
PR118  1m_4  [RC0402]  35.4 58.9 90 bottom
PR119  1m_4  [RC0402]  36.54 58.9 270 bottom
PR120  6.65k/f_4  [RC0402]  31.72 57.94 180 bottom
PR121  1.78k/f_4  [RC0402]  126.85 57.2 90 bottom
PR122  10k/f_4  [RC0402]  31.72 56.92 0 bottom
PR123  *0/short_4  [SHORT0402]  34.13 56.54 270 bottom
PR124  499/f_4  [RC0402]  126.33 55.02 0 bottom
PR125  *22_8  [RC0805]  129.12 55.02 0 bottom
PR126  *0/short_4  [SHORT0402]  31.74 54.13 0 bottom
PR127  22_8  [RC0805]  29.56 53.11 270 bottom
PR128  *0/short_4  [SHORT0402]  31.61 52.86 180 bottom
PR129  1m_4  [RC0402]  22.95 52.48 90 bottom
PR130  1m_4  [RC0402]  23.97 52.48 270 bottom
PR132  *0/short_4  [SHORT0402]  43.69 51.21 0 bottom
PR133  *0/short_4  [SHORT0402]  144.49 51.08 90 bottom
PR134  1m_6  [RC0603]  142.97 50.7 270 bottom
PR135  22_8  [RC0805]  140.43 51.33 0 bottom
PR136  1m_4  [RC0402]  147.29 49.94 90 bottom
PR137  1m_4  [RC0402]  148.43 49.94 270 bottom
PR138  15k/f_4  [RC0402]  43.77 48.95 0 bottom
PR139  11.3k/f_4  [RC0402]  43.77 47.93 0 bottom
PR140  10k_4  [RC0402]  38.88 46.51 90 bottom
PR141  *0/short_4  [SHORT0402]  45.48 48.32 90 bottom
PR142  *1m_4  [RC0402]  126.33 45.75 180 bottom
PR143  *1m_4  [RC0402]  128.62 45.75 180 bottom
PR144  *0/short_4  [SHORT0402]  156.15 44.83 270 bottom
PR145  *0/short_4  [SHORT0402]  123.21 45.47 180 bottom
PR146  *2.2_6  [RC0603]  117.57 44.22 90 bottom
PR147  *0/short_4  [SHORT0402]  122.52 43.41 0 bottom
PR148  *0_4  [RC0402]  122.52 42.32 180 bottom
PR150  91k/f_4  [RC0402]  35.86 41.38 90 bottom
PR151  100k/f_4  [RC0402]  36.87 41.38 90 bottom
PR152  *0/short_4  [SHORT0402]  23.28 40.67 180 bottom
PR153  20k/f_4  [RC0402]  25.42 39.9 0 bottom
PR154  *0/short_4  [SHORT0402]  26.03 39.52 90 top
PR155  *0/short_4  [SHORT0402]  25.49 38.86 0 bottom
PR157  *2.2_6  [RC0603]  154.47 39.62 0 bottom
PR158  10k/f_4  [RC0402]  29.25 36.17 90 bottom
PR159  *0/short_4  [SHORT0402]  36.08 35.13 180 bottom
PR161  *0/short_4  [SHORT0402]  29.28 34.54 180 bottom
PR162  *0/short_4  [SHORT0402]  36.08 34.11 180 bottom
PR163  *0/short_4  [SHORT0402]  149.19 33.81 0 bottom
PR164  *0/short_4  [SHORT0402]  149.19 32.66 180 bottom
PR166  1m_6  [RC0603]  46.19 25.81 0 bottom
PR167  *2.2_6  [RC0603]  31.26 24.92 180 bottom
PR168  200k_6  [RC0603]  42.76 23.77 90 bottom
PR169  *0/short_6  [SHORT0603]  44.03 23.77 90 bottom
PR170  10k/f_4_4250ntc  [RC0402]  95.57 49.12 0 top
PR171  200k/f_4  [RC0402]  37.43 17.55 90 bottom
PR172  200k/f_4  [RC0402]  38.57 17.55 270 bottom
PR173  1.5k/f_4  [RC0402]  39.72 17.55 270 bottom
PR174  100k/j_4  [RC0402]  68.42 16.79 0 bottom
PR175  *0/short_4  [SHORT0402]  77.56 16.28 0 bottom
PR176  *0/short_4  [SHORT0402]  77.56 15.14 180 bottom
PR177  *0/short_4  [SHORT0402]  67.28 15.65 180 bottom
PR178  100/j_4  [RC0402]  69.05 15.27 90 bottom
PR179  100/j_4  [RC0402]  70.2 15.27 270 bottom
PR180  100/j_4  [RC0402]  74.13 16.28 270 bottom
PR181  *0/short_4  [SHORT0402]  77.56 14.12 180 bottom
PR182  *22_6  [RC0603]  85.15 11.68 180 bottom
PR183  *0/short_4  [SHORT0402]  81.25 10.95 90 bottom
PR184  20k/f_4  [RC0402]  83.28 10.95 90 bottom
PR185  22_6  [RC0603]  85.15 10.41 180 bottom
PU6  apw8804  [DFN10-3X3-5-11P-SYF554DBC]  30.46 55.04 0 top
PU7  apw8804  [DFN10-3X3-5-11P-SYF554DBC]  113.35 53.99 0 top
PU8  nb670  [QFN14-3X3-4-16P]  119.42 46.16 270 top
PU9  apw8819qai  [TQFN20-3X3-4-21P]  32.23 35.42 270 top
PU10  nb671gq-z  [QFN14-3X3-4-16P]  152.98 33.75 90 top
PU11  oz8691ln-b  [VQFN40-5X5-4-57P]  138.39 20.7 90 top
PU12  isl95833hrtz-t  [QFN32-4X4-4-33P-ISL95812HRZ-SMT]  127.71 65.33 270 bottom
PU13  apw8824  [TSOP6-2_8-95]  39.33 49.46 180 bottom
PU14  g9661  [SOP8-6-1_27-9P]  30.82 42.47 90 bottom
PU15  as393mtr-e1  [SOIC8-6-1_27]  39.21 23.01 180 bottom
PU16  g5934rz1u  [TQFN20-3X3-4-21P]  81 14.73 90 bottom
Q6  pj4n3kdw  [SC70-2_1-65-6P]  58.89 89.31 180 top
Q7  2n7002dw  [SC70-2_1-65-6P]  22.7 80.43 0 top
Q8  pja138k  [SOT23_213-3_3-2]  41.65 74.17 180 top
Q11  pja138k  [SOT23_213-3_3-2]  32.48 73.18 90 top
Q12  *pja138k  [SOT23_213-3_3-2]  45.81 52.86 0 top
Q13  dtc144eua  [UMT_213-3-1_3]  162.74 93.88 180 bottom
Q14  2n7002  [SOT23_213-3_3-2]  65.88 86.51 180 bottom
Q15  2n7002k  [SOT23_213-3_3-2]  69.82 86.51 0 bottom
Q16  *2n7002dw  [SC70-2_1-65-6P]  159.63 84.33 180 bottom
Q17  ap2331sa-7  [SOT23_213-3_3-2]  59.66 83.46 180 bottom
Q18  *pja138k  [SOT23_213-3_3-2]  85.31 81.43 0 bottom
Q19  pja138k  [SOT23_213-3_3-2]  160.83 79.15 180 bottom
Q20  *pja138k  [SOT23_213-3_3-2]  160.83 75.59 180 bottom
Q21  pj4n3kdw  [SC70-2_1-65-6P]  94.2 74.47 270 bottom
Q23  pj4n3kdw  [SC70-2_1-65-6P]  94.2 70 270 bottom
Q24  pj4n3kdw  [SC70-2_1-65-6P]  97.35 67.23 90 bottom
Q25  *pja138k  [SOT23_213-3_3-2]  153.64 66.95 90 bottom
Q27  pja138k  [SOT23_213-3_3-2]  33.87 76.99 0 top
Q28  2n7002k  [SOT23_213-3_3-2]  35.25 61.85 90 bottom
Q29  pj4n3kdw  [SC70-2_1-65-6P]  85.93 58.43 180 bottom
Q30  pja138k  [SOT23_213-3_3-2]  149.44 58.01 180 bottom
